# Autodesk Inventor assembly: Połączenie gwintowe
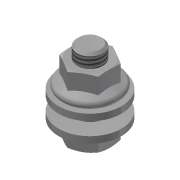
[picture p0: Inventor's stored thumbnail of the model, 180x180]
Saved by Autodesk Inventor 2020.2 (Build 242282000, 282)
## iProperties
Manager: www.cadconsulting.pl
Company: Fabian Stasiak CAD Consulting
ClientObjectVersion: 1
Created: 2011-01
Part Number: Połączenie gwintowe
Document SubType Name: Assembly
Designer: F.Stasiak
Author: F.Stasiak
Subject: Zbiór ćwiczeń. Autodesk Inventor 2020. Kurs podstawowy
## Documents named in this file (4)
- C:\2020_Kurs_podstawowy\R6 Zespoły\Kolizja\100-000\Design Accelerator\Połączenie gwintowe2.iam
- C:\2020_Kurs_podstawowy\Zasoby\Content Center Files\pl-PL\DIN 6796\DIN 6796 - 12.ipt
- C:\2020_Kurs_podstawowy\Zasoby\Content Center Files\pl-PL\DIN EN 24 017\ISO 4017 - M12 x 30DIN EN.ipt
- C:\2020_Kurs_podstawowy\Zasoby\Content Center Files\pl-PL\DIN 6923\DIN 6923 - M12 x 1,75.ipt
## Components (4 placed, 3 different names)
1. DIN 6796 12:1
2. DIN EN 24017 M12 x 30:1
3. DIN 6796 12:2
4. DIN 6923 M12:1
